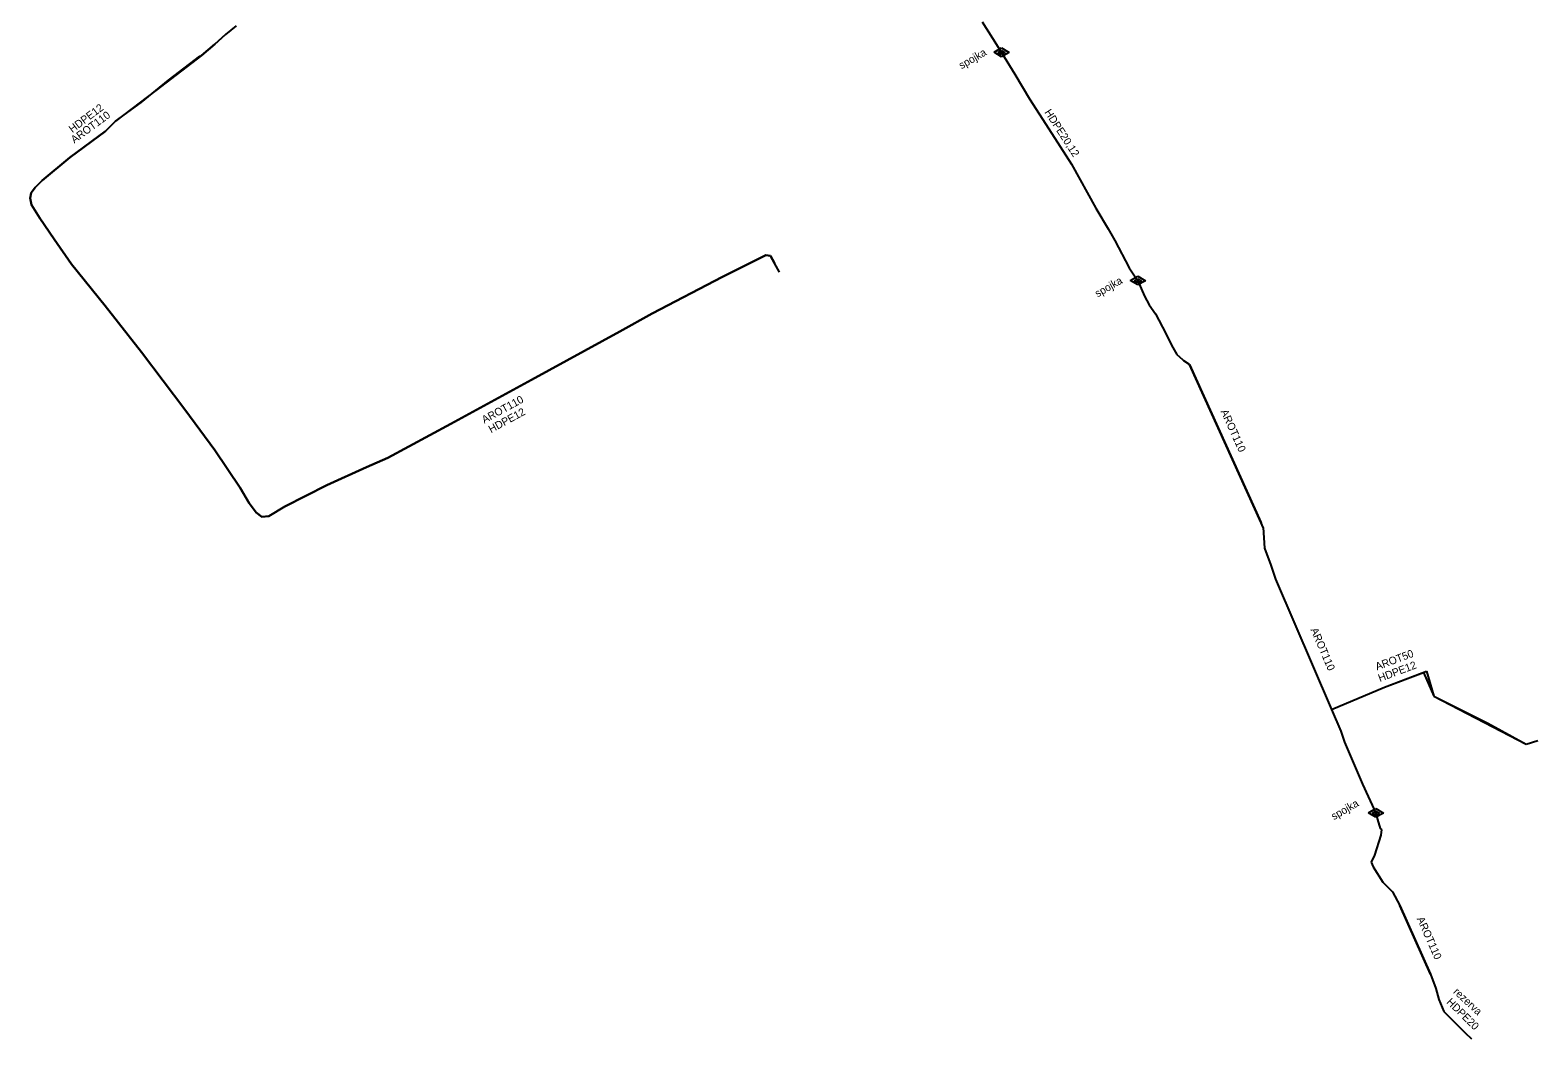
# Model space of a CAD drawing. Extents: x -651943 to -618711, y -1138561 to -1100552.
# Drawn here: x -640569.3 to -640422, y -1115998.4 to -1115899.7 of the extents above; entities that cross this region are included whole.
import ezdxf

# ---------------------------------------------------------------- set-up
doc = ezdxf.new("R2010")
doc.units = 0
for name, color, linetype in [('KT optika', 7, 'Continuous'), ('KT trasa', 7, 'Continuous'), ('KT zařízení', 7, 'Continuous')]:
    doc.layers.add(name, color=color, linetype=linetype)

# ---------------------------------------------------------------- blocks, each defined once
blk = doc.blocks.new('TVSPO_1')
at = {"layer": 'KT zařízení'}
for p, q in [((-0.074, 0.002), (0, 0.044)), ((-0.001, -0.041), (-0.074, 0.002)), ((-0.035, 0), (0, 0.02)), ((0.073, 0.001), (-0.001, -0.041)), ((0, 0.044), (0.073, 0.001)), ((0, 0.02), (0.035, 0)), ((0.035, 0), (0, -0.02)), ((0, -0.02), (-0.035, 0))]:
    blk.add_line(p, q, dxfattribs=at)

msp = doc.modelspace()

# ---------------------------------------------------------------- linework, layer by layer
at = {"layer": 'KT optika'}
for p, q in [((-640549.17, -1115899.3), (-640550.23, -1115900.17)), ((-640476.26, -1115898.91), (-640475.25, -1115900.51)), ((-640552.58, -1115902.2), (-640551.28, -1115901.12)), ((-640551.28, -1115901.12), (-640550.23, -1115900.17)), ((-640555.81, -1115904.61), (-640552.75, -1115902.27)), ((-640552.75, -1115902.27), (-640552.58, -1115902.2)), ((-640473.09, -1115904.05), (-640471.64, -1115906.45)), ((-640558.47, -1115906.81), (-640557.04, -1115905.64)), ((-640557.04, -1115905.64), (-640555.81, -1115904.61)), ((-640560.97, -1115908.65), (-640558.47, -1115906.81)), ((-640471.64, -1115906.45), (-640469.76, -1115909.37)), ((-640561.97, -1115909.61), (-640560.97, -1115908.65)), ((-640565.43, -1115912.2), (-640561.97, -1115909.61)), ((-640469.76, -1115909.37), (-640467.54, -1115912.85)), ((-640568.15, -1115914.45), (-640565.43, -1115912.2)), ((-640467.54, -1115912.85), (-640465.16, -1115917.15)), ((-640568.84, -1115915.11), (-640568.15, -1115914.45)), ((-640569.32, -1115916.17), (-640569.21, -1115915.64)), ((-640569.18, -1115916.82), (-640569.32, -1115916.17)), ((-640569.21, -1115915.64), (-640568.84, -1115915.11)), ((-640568.39, -1115918.13), (-640569.18, -1115916.82)), ((-640465.16, -1115917.15), (-640463.96, -1115919.15)), ((-640566.98, -1115920.17), (-640568.39, -1115918.13)), ((-640463.96, -1115919.15), (-640463.29, -1115920.3)), ((-640565.29, -1115922.61), (-640566.98, -1115920.17)), ((-640463.29, -1115920.3), (-640461.91, -1115922.96)), ((-640498.14, -1115922.09), (-640501.65, -1115923.87)), ((-640497.42, -1115921.73), (-640498.14, -1115922.09)), ((-640496.96, -1115921.81), (-640497.42, -1115921.73)), ((-640496.56, -1115922.53), (-640496.96, -1115921.81)), ((-640562, -1115926.69), (-640565.29, -1115922.61)), ((-640496.09, -1115923.4), (-640496.56, -1115922.53)), ((-640501.65, -1115923.87), (-640508.51, -1115927.44)), ((-640460.4, -1115925.75), (-640459.95, -1115926.59)), ((-640558.44, -1115931.23), (-640562, -1115926.69)), ((-640508.51, -1115927.44), (-640511.67, -1115929.21)), ((-640459.95, -1115926.59), (-640459.33, -1115927.48)), ((-640459.33, -1115927.48), (-640458.31, -1115929.39)), ((-640511.67, -1115929.21), (-640520.31, -1115933.92)), ((-640458.31, -1115929.39), (-640457.77, -1115930.55)), ((-640457.77, -1115930.55), (-640457.24, -1115931.44)), ((-640554.21, -1115936.81), (-640558.44, -1115931.23)), ((-640457.24, -1115931.44), (-640456.69, -1115931.95)), ((-640456.69, -1115931.95), (-640456.57, -1115932.08)), ((-640455.99, -1115932.43), (-640456.57, -1115932.08)), ((-640455.99, -1115932.43), (-640449, -1115947.91)), ((-640520.31, -1115933.92), (-640528.19, -1115938.22)), ((-640551.28, -1115940.8), (-640554.21, -1115936.81)), ((-640528.19, -1115938.22), (-640534.35, -1115941.56)), ((-640548.78, -1115944.47), (-640551.28, -1115940.8)), ((-640536.45, -1115942.48), (-640540.32, -1115944.23)), ((-640534.35, -1115941.56), (-640536.45, -1115942.48)), ((-640547.92, -1115945.97), (-640548.78, -1115944.47)), ((-640540.32, -1115944.23), (-640544.43, -1115946.31)), ((-640547.23, -1115946.91), (-640547.92, -1115945.97)), ((-640546.69, -1115947.33), (-640547.23, -1115946.91)), ((-640544.43, -1115946.31), (-640545.98, -1115947.24)), ((-640545.98, -1115947.24), (-640546.69, -1115947.33)), ((-640448.82, -1115948.36), (-640449, -1115947.91)), ((-640448.82, -1115948.36), (-640448.68, -1115950.4)), ((-640448.68, -1115950.4), (-640448.07, -1115952.06)), ((-640448.07, -1115952.06), (-640447.6, -1115953.4)), ((-640447.6, -1115953.4), (-640442.12, -1115966.16)), ((-640436.95, -1115963.97), (-640433.13, -1115962.54)), ((-640433.13, -1115962.54), (-640432.12, -1115964.84)), ((-640442.12, -1115966.16), (-640436.95, -1115963.97)), ((-640432.12, -1115964.84), (-640426.86, -1115967.49)), ((-640442.12, -1115966.16), (-640441.2, -1115968.27)), ((-640426.86, -1115967.49), (-640423.1, -1115969.55)), ((-640441.2, -1115968.27), (-640440.85, -1115969.34)), ((-640423.1, -1115969.55), (-640421.96, -1115969.19)), ((-640440.85, -1115969.34), (-640439.09, -1115973.47)), ((-640437.62, -1115976.92), (-640437.36, -1115977.8)), ((-640437.36, -1115977.8), (-640437.25, -1115977.9)), ((-640437.25, -1115977.9), (-640437.29, -1115978.45)), ((-640437.29, -1115978.45), (-640437.91, -1115980.41)), ((-640437.91, -1115980.41), (-640438.26, -1115981.1)), ((-640438.26, -1115981.1), (-640438.06, -1115981.54)), ((-640438.06, -1115981.54), (-640437.1, -1115983.03)), ((-640437.1, -1115983.03), (-640436.18, -1115984)), ((-640436.18, -1115984), (-640435.44, -1115985.31)), ((-640435.44, -1115985.31), (-640432.46, -1115992.03)), ((-640432.46, -1115992.03), (-640431.93, -1115993.45)), ((-640431.93, -1115993.45), (-640431.65, -1115994.52)), ((-640431.65, -1115994.52), (-640431.16, -1115995.7)), ((-640431.16, -1115995.7), (-640430.07, -1115996.77)), ((-640430.07, -1115996.77), (-640429.06, -1115997.77)), ((-640429.06, -1115997.77), (-640428.43, -1115998.36))]:
    msp.add_line(p, q, dxfattribs=at)
for points in [[(-640475.25, -1115900.51), (-640474.37, -1115901.92), (-640473.09, -1115904.05)], [(-640461.91, -1115922.96), (-640461.05, -1115924.24), (-640460.4, -1115925.75)], [(-640439.09, -1115973.47), (-640437.78, -1115976.29), (-640437.62, -1115976.92)]]:
    msp.add_lwpolyline(points, dxfattribs=at)
at = {"layer": 'KT trasa'}
for p, q in [((-640549.17, -1115899.3), (-640550.23, -1115900.17)), ((-640476.26, -1115898.91), (-640475.25, -1115900.51)), ((-640552.58, -1115902.2), (-640551.28, -1115901.12)), ((-640551.28, -1115901.12), (-640550.23, -1115900.17)), ((-640555.81, -1115904.61), (-640552.75, -1115902.27)), ((-640552.75, -1115902.27), (-640552.58, -1115902.2)), ((-640473.09, -1115904.05), (-640471.64, -1115906.45)), ((-640558.47, -1115906.81), (-640557.04, -1115905.64)), ((-640557.04, -1115905.64), (-640555.81, -1115904.61)), ((-640560.97, -1115908.65), (-640558.47, -1115906.81)), ((-640471.64, -1115906.45), (-640469.76, -1115909.37)), ((-640561.97, -1115909.61), (-640560.97, -1115908.65)), ((-640565.43, -1115912.2), (-640561.97, -1115909.61)), ((-640469.76, -1115909.37), (-640467.54, -1115912.85)), ((-640568.15, -1115914.45), (-640565.43, -1115912.2)), ((-640467.54, -1115912.85), (-640465.16, -1115917.15)), ((-640568.84, -1115915.11), (-640568.15, -1115914.45)), ((-640569.32, -1115916.17), (-640569.21, -1115915.64)), ((-640569.18, -1115916.82), (-640569.32, -1115916.17)), ((-640569.21, -1115915.64), (-640568.84, -1115915.11)), ((-640568.39, -1115918.13), (-640569.18, -1115916.82)), ((-640465.16, -1115917.15), (-640463.96, -1115919.15)), ((-640566.98, -1115920.17), (-640568.39, -1115918.13)), ((-640463.96, -1115919.15), (-640463.29, -1115920.3)), ((-640565.29, -1115922.61), (-640566.98, -1115920.17)), ((-640463.29, -1115920.3), (-640461.91, -1115922.96)), ((-640498.14, -1115922.09), (-640501.65, -1115923.87)), ((-640497.42, -1115921.73), (-640498.14, -1115922.09)), ((-640496.96, -1115921.81), (-640497.42, -1115921.73)), ((-640496.56, -1115922.53), (-640496.96, -1115921.81)), ((-640562, -1115926.69), (-640565.29, -1115922.61)), ((-640496.09, -1115923.4), (-640496.56, -1115922.53)), ((-640501.65, -1115923.87), (-640508.51, -1115927.44)), ((-640460.4, -1115925.75), (-640459.95, -1115926.59)), ((-640558.44, -1115931.23), (-640562, -1115926.69)), ((-640508.51, -1115927.44), (-640511.67, -1115929.21)), ((-640459.95, -1115926.59), (-640459.33, -1115927.48)), ((-640459.33, -1115927.48), (-640458.31, -1115929.39)), ((-640511.67, -1115929.21), (-640520.31, -1115933.92)), ((-640458.31, -1115929.39), (-640457.77, -1115930.55)), ((-640457.77, -1115930.55), (-640457.24, -1115931.44)), ((-640554.21, -1115936.81), (-640558.44, -1115931.23)), ((-640457.24, -1115931.44), (-640456.69, -1115931.95)), ((-640456.69, -1115931.95), (-640456.57, -1115932.08)), ((-640455.99, -1115932.43), (-640456.57, -1115932.08)), ((-640455.99, -1115932.43), (-640449, -1115947.91)), ((-640520.31, -1115933.92), (-640528.19, -1115938.22)), ((-640551.28, -1115940.8), (-640554.21, -1115936.81)), ((-640528.19, -1115938.22), (-640534.35, -1115941.56)), ((-640548.78, -1115944.47), (-640551.28, -1115940.8)), ((-640536.45, -1115942.48), (-640540.32, -1115944.23)), ((-640534.35, -1115941.56), (-640536.45, -1115942.48)), ((-640547.92, -1115945.97), (-640548.78, -1115944.47)), ((-640540.32, -1115944.23), (-640544.43, -1115946.31)), ((-640547.23, -1115946.91), (-640547.92, -1115945.97)), ((-640546.69, -1115947.33), (-640547.23, -1115946.91)), ((-640544.43, -1115946.31), (-640545.98, -1115947.24)), ((-640545.98, -1115947.24), (-640546.69, -1115947.33)), ((-640448.82, -1115948.36), (-640449, -1115947.91)), ((-640448.82, -1115948.36), (-640448.68, -1115950.4)), ((-640448.68, -1115950.4), (-640448.07, -1115952.06)), ((-640448.07, -1115952.06), (-640447.6, -1115953.4)), ((-640447.6, -1115953.4), (-640442.12, -1115966.16)), ((-640436.95, -1115963.97), (-640433.13, -1115962.54)), ((-640433.13, -1115962.54), (-640432.12, -1115964.84)), ((-640442.12, -1115966.16), (-640436.95, -1115963.97)), ((-640432.12, -1115964.84), (-640426.86, -1115967.49)), ((-640442.12, -1115966.16), (-640441.2, -1115968.27)), ((-640426.86, -1115967.49), (-640423.1, -1115969.55)), ((-640441.2, -1115968.27), (-640440.85, -1115969.34)), ((-640423.1, -1115969.55), (-640421.96, -1115969.19)), ((-640440.85, -1115969.34), (-640439.09, -1115973.47)), ((-640437.62, -1115976.92), (-640437.36, -1115977.8)), ((-640437.36, -1115977.8), (-640437.25, -1115977.9)), ((-640437.25, -1115977.9), (-640437.29, -1115978.45)), ((-640437.29, -1115978.45), (-640437.91, -1115980.41)), ((-640437.91, -1115980.41), (-640438.26, -1115981.1)), ((-640438.26, -1115981.1), (-640438.06, -1115981.54)), ((-640438.06, -1115981.54), (-640437.1, -1115983.03)), ((-640437.1, -1115983.03), (-640436.18, -1115984)), ((-640436.18, -1115984), (-640435.44, -1115985.31)), ((-640435.44, -1115985.31), (-640432.46, -1115992.03)), ((-640432.46, -1115992.03), (-640431.93, -1115993.45)), ((-640431.93, -1115993.45), (-640431.65, -1115994.52)), ((-640431.65, -1115994.52), (-640431.16, -1115995.7)), ((-640431.16, -1115995.7), (-640430.07, -1115996.77)), ((-640430.07, -1115996.77), (-640429.06, -1115997.77)), ((-640429.06, -1115997.77), (-640428.43, -1115998.36))]:
    msp.add_line(p, q, dxfattribs=at)
for points in [[(-640475.25, -1115900.51), (-640474.37, -1115901.92), (-640473.09, -1115904.05)], [(-640461.91, -1115922.96), (-640461.05, -1115924.24), (-640460.4, -1115925.75)], [(-640439.09, -1115973.47), (-640437.78, -1115976.29), (-640437.62, -1115976.92)]]:
    msp.add_lwpolyline(points, dxfattribs=at)
at = {"layer": 'KT zařízení'}
for p, q in [((-640549.17, -1115899.3), (-640550.23, -1115900.17)), ((-640476.26, -1115898.91), (-640475.25, -1115900.51)), ((-640551.28, -1115901.12), (-640552.58, -1115902.2)), ((-640552.58, -1115902.2), (-640551.28, -1115901.12)), ((-640550.23, -1115900.17), (-640551.28, -1115901.12)), ((-640551.28, -1115901.12), (-640550.23, -1115900.17)), ((-640552.58, -1115902.2), (-640557.04, -1115905.64)), ((-640555.81, -1115904.61), (-640552.75, -1115902.27)), ((-640552.75, -1115902.27), (-640552.58, -1115902.2)), ((-640473.09, -1115904.05), (-640471.64, -1115906.45)), ((-640557.04, -1115905.64), (-640560.97, -1115908.65)), ((-640558.47, -1115906.81), (-640557.04, -1115905.64)), ((-640557.04, -1115905.64), (-640555.81, -1115904.61)), ((-640560.97, -1115908.65), (-640558.47, -1115906.81)), ((-640471.64, -1115906.45), (-640469.76, -1115909.37)), ((-640561.97, -1115909.61), (-640560.97, -1115908.65)), ((-640560.97, -1115908.65), (-640561.97, -1115909.61)), ((-640561.97, -1115909.61), (-640565.43, -1115912.2)), ((-640565.43, -1115912.2), (-640561.97, -1115909.61)), ((-640469.76, -1115909.37), (-640467.54, -1115912.85)), ((-640565.43, -1115912.2), (-640568.15, -1115914.45)), ((-640568.15, -1115914.45), (-640565.43, -1115912.2)), ((-640467.54, -1115912.85), (-640465.16, -1115917.15)), ((-640568.15, -1115914.45), (-640568.84, -1115915.11)), ((-640568.84, -1115915.11), (-640568.15, -1115914.45)), ((-640569.21, -1115915.64), (-640569.32, -1115916.17)), ((-640569.32, -1115916.17), (-640569.21, -1115915.64)), ((-640569.32, -1115916.17), (-640569.18, -1115916.82)), ((-640569.18, -1115916.82), (-640569.32, -1115916.17)), ((-640568.84, -1115915.11), (-640569.21, -1115915.64)), ((-640569.21, -1115915.64), (-640568.84, -1115915.11)), ((-640569.18, -1115916.82), (-640568.39, -1115918.13)), ((-640568.39, -1115918.13), (-640569.18, -1115916.82)), ((-640465.16, -1115917.15), (-640463.96, -1115919.15)), ((-640568.39, -1115918.13), (-640566.98, -1115920.17)), ((-640566.98, -1115920.17), (-640568.39, -1115918.13)), ((-640463.96, -1115919.15), (-640463.29, -1115920.3)), ((-640566.98, -1115920.17), (-640565.29, -1115922.61)), ((-640565.29, -1115922.61), (-640566.98, -1115920.17)), ((-640463.29, -1115920.3), (-640461.91, -1115922.96)), ((-640501.65, -1115923.87), (-640498.14, -1115922.09)), ((-640498.14, -1115922.09), (-640501.65, -1115923.87)), ((-640498.14, -1115922.09), (-640497.42, -1115921.73)), ((-640497.42, -1115921.73), (-640498.14, -1115922.09)), ((-640497.42, -1115921.73), (-640496.96, -1115921.81)), ((-640496.96, -1115921.81), (-640497.42, -1115921.73)), ((-640496.96, -1115921.81), (-640496.56, -1115922.53)), ((-640496.56, -1115922.53), (-640496.96, -1115921.81)), ((-640565.29, -1115922.61), (-640562, -1115926.69)), ((-640562, -1115926.69), (-640565.29, -1115922.61)), ((-640496.09, -1115923.4), (-640496.56, -1115922.53)), ((-640508.51, -1115927.44), (-640501.65, -1115923.87)), ((-640501.65, -1115923.87), (-640508.51, -1115927.44)), ((-640460.4, -1115925.75), (-640459.95, -1115926.59)), ((-640562, -1115926.69), (-640558.44, -1115931.23)), ((-640558.44, -1115931.23), (-640562, -1115926.69)), ((-640511.67, -1115929.21), (-640508.51, -1115927.44)), ((-640508.51, -1115927.44), (-640511.67, -1115929.21)), ((-640459.95, -1115926.59), (-640459.33, -1115927.48)), ((-640459.33, -1115927.48), (-640458.31, -1115929.39)), ((-640520.31, -1115933.92), (-640511.67, -1115929.21)), ((-640511.67, -1115929.21), (-640520.31, -1115933.92)), ((-640458.31, -1115929.39), (-640457.77, -1115930.55)), ((-640457.77, -1115930.55), (-640457.24, -1115931.44)), ((-640558.44, -1115931.23), (-640554.21, -1115936.81)), ((-640554.21, -1115936.81), (-640558.44, -1115931.23)), ((-640457.24, -1115931.44), (-640456.69, -1115931.95)), ((-640456.69, -1115931.95), (-640456.57, -1115932.08)), ((-640455.99, -1115932.43), (-640456.57, -1115932.08)), ((-640449, -1115947.91), (-640455.99, -1115932.43)), ((-640455.99, -1115932.43), (-640449, -1115947.91)), ((-640528.19, -1115938.22), (-640520.31, -1115933.92)), ((-640520.31, -1115933.92), (-640528.19, -1115938.22)), ((-640554.21, -1115936.81), (-640551.28, -1115940.8)), ((-640551.28, -1115940.8), (-640554.21, -1115936.81)), ((-640534.35, -1115941.56), (-640528.19, -1115938.22)), ((-640528.19, -1115938.22), (-640534.35, -1115941.56)), ((-640551.28, -1115940.8), (-640548.78, -1115944.47)), ((-640548.78, -1115944.47), (-640551.28, -1115940.8)), ((-640540.32, -1115944.23), (-640536.45, -1115942.48)), ((-640536.45, -1115942.48), (-640540.32, -1115944.23)), ((-640536.45, -1115942.48), (-640534.35, -1115941.56)), ((-640534.35, -1115941.56), (-640536.45, -1115942.48)), ((-640548.78, -1115944.47), (-640547.92, -1115945.97)), ((-640547.92, -1115945.97), (-640548.78, -1115944.47)), ((-640544.43, -1115946.31), (-640540.32, -1115944.23)), ((-640540.32, -1115944.23), (-640544.43, -1115946.31)), ((-640547.92, -1115945.97), (-640547.23, -1115946.91)), ((-640547.23, -1115946.91), (-640547.92, -1115945.97)), ((-640547.23, -1115946.91), (-640546.69, -1115947.33)), ((-640546.69, -1115947.33), (-640547.23, -1115946.91)), ((-640545.98, -1115947.24), (-640544.43, -1115946.31)), ((-640544.43, -1115946.31), (-640545.98, -1115947.24)), ((-640546.69, -1115947.33), (-640545.98, -1115947.24)), ((-640545.98, -1115947.24), (-640546.69, -1115947.33)), ((-640448.82, -1115948.36), (-640449, -1115947.91)), ((-640448.82, -1115948.36), (-640448.68, -1115950.4)), ((-640448.68, -1115950.4), (-640448.07, -1115952.06)), ((-640448.07, -1115952.06), (-640447.6, -1115953.4)), ((-640447.6, -1115953.4), (-640442.12, -1115966.16)), ((-640447.6, -1115953.4), (-640442.12, -1115966.16)), ((-640436.95, -1115963.97), (-640432.83, -1115962.42)), ((-640436.95, -1115963.97), (-640433.13, -1115962.54)), ((-640433.13, -1115962.54), (-640432.12, -1115964.84)), ((-640432.83, -1115962.42), (-640432.12, -1115964.84)), ((-640442.12, -1115966.16), (-640436.95, -1115963.97)), ((-640442.12, -1115966.16), (-640436.95, -1115963.97)), ((-640432.12, -1115964.84), (-640426.86, -1115967.49)), ((-640432.12, -1115964.84), (-640423.1, -1115969.55)), ((-640442.12, -1115966.16), (-640441.2, -1115968.27)), ((-640426.86, -1115967.49), (-640423.1, -1115969.55)), ((-640441.2, -1115968.27), (-640440.85, -1115969.34)), ((-640423.1, -1115969.55), (-640421.96, -1115969.19)), ((-640423.1, -1115969.55), (-640421.96, -1115969.19)), ((-640440.85, -1115969.34), (-640439.09, -1115973.47)), ((-640437.62, -1115976.92), (-640437.36, -1115977.8)), ((-640437.36, -1115977.8), (-640437.25, -1115977.9)), ((-640437.25, -1115977.9), (-640437.29, -1115978.45)), ((-640437.29, -1115978.45), (-640437.91, -1115980.41)), ((-640437.91, -1115980.41), (-640438.26, -1115981.1)), ((-640438.26, -1115981.1), (-640438.06, -1115981.54)), ((-640438.06, -1115981.54), (-640437.1, -1115983.03)), ((-640437.1, -1115983.03), (-640436.18, -1115984)), ((-640436.18, -1115984), (-640435.44, -1115985.31)), ((-640435.44, -1115985.31), (-640432.46, -1115992.03)), ((-640432.46, -1115992.03), (-640435.44, -1115985.31)), ((-640432.46, -1115992.03), (-640431.93, -1115993.45)), ((-640431.93, -1115993.45), (-640431.65, -1115994.52)), ((-640431.65, -1115994.52), (-640431.16, -1115995.7)), ((-640431.16, -1115995.7), (-640430.07, -1115996.77)), ((-640430.07, -1115996.77), (-640429.06, -1115997.77)), ((-640429.06, -1115997.77), (-640428.43, -1115998.36))]:
    msp.add_line(p, q, dxfattribs=at)
for points in [[(-640475.25, -1115900.51), (-640474.37, -1115901.92), (-640473.09, -1115904.05)], [(-640461.91, -1115922.96), (-640461.05, -1115924.24), (-640460.4, -1115925.75)], [(-640439.09, -1115973.47), (-640437.78, -1115976.29), (-640437.62, -1115976.92)]]:
    msp.add_lwpolyline(points, dxfattribs=at)

# ---------------------------------------------------------------- block references
at = {"layer": 'KT zařízení', "xscale": 10, "yscale": 10}
for p in [(-640474.37, -1115901.92), (-640461.05, -1115924.24), (-640437.78, -1115976.29)]:
    msp.add_blockref('TVSPO_1', p, dxfattribs=at)

# ---------------------------------------------------------------- texts
at = {"layer": 'KT zařízení'}
for s, rotation, p in [('spojka', 29.9794, (-640478.29, -1115903.57)), ('HDPE12', 36.8169, (-640565.2, -1115909.81)), ('AROT110', 36.3531, (-640565, -1115910.84)), ('HDPE20,12', 302.7749, (-640470.21, -1115907.76)), ('spojka', 29.9794, (-640464.99, -1115925.88)), ('AROT110', 28.5965, (-640524.93, -1115938.21)), ('HDPE12', 28.6206, (-640524.27, -1115939.15)), ('AROT110', 294.3016, (-640452.98, -1115937.01)), ('AROT110', 293.2419, (-640444.19, -1115958.35)), ('AROT50', 20.5232, (-640437.68, -1115962.34)), ('HDPE12', 20.5232, (-640437.4, -1115963.47)), ('spojka', 29.9794, (-640441.9, -1115976.99)), ('AROT110', 293.915, (-640433.81, -1115986.61)), ('rezerva', 316.8779, (-640430.28, -1115993.83)), ('HDPE20', 315.5305, (-640430.94, -1115994.83))]:
    msp.add_text(s, height=0.75, rotation=rotation, dxfattribs=at).set_placement(p)

doc.saveas('drawing.dxf')
